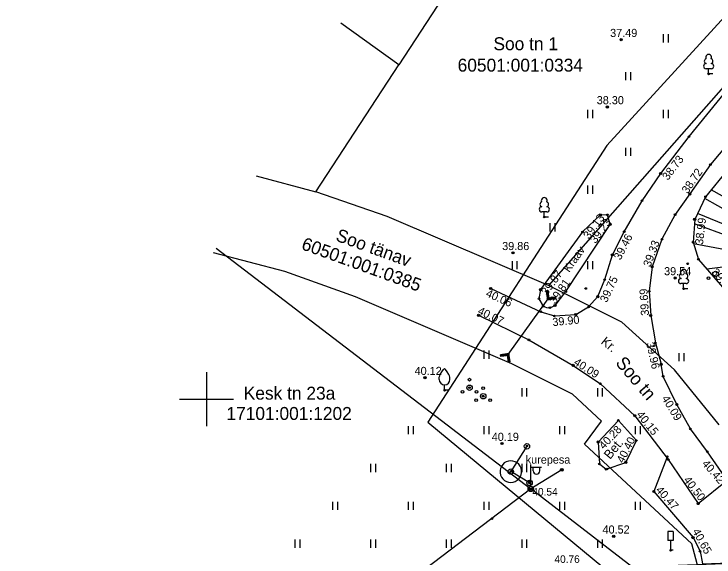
# Model space of a CAD drawing. Extents: x 641898 to 642452, y 6471715 to 6472255.
# Drawn here: x 641932.2 to 641997, y 6472085.4 to 6472135.7 of the extents above; entities that cross this region are included whole.
import ezdxf

# ---------------------------------------------------------------- set-up
doc = ezdxf.new("R2010")
doc.units = 0
for name, color, linetype in [('HALJASTUS', 7, 'Continuous'), ('KORGUS-EH2000', 7, 'Continuous'), ('LIIKLUS', 7, 'Continuous'), ('MOOTMPUNKT', 7, 'Continuous'), ('MOOTPIIR', 7, 'Continuous'), ('MPOHULIIN', 7, 'Continuous'), ('PIIR', 7, 'Continuous'), ('POST', 7, 'Continuous'), ('PUU', 7, 'Continuous'), ('RAJATIS', 7, 'Continuous'), ('RELJEEF', 7, 'Continuous'), ('TEE', 7, 'Continuous'), ('TRUUP', 7, 'Continuous'), ('VEEKOGU', 7, 'Continuous'), ('VORK', 7, 'Continuous')]:
    doc.layers.add(name, color=color, linetype=linetype)

msp = doc.modelspace()

# ---------------------------------------------------------------- linework, layer by layer
at = {"layer": 'HALJASTUS'}
for p, q in [((641992.275, 6472133.795), (641992.275, 6472133.034)), ((641992.73, 6472133.795), (641992.73, 6472133.034)), ((641988.775, 6472130.295), (641988.775, 6472129.534)), ((641989.23, 6472130.295), (641989.23, 6472129.534)), ((641985.275, 6472126.795), (641985.275, 6472126.034)), ((641985.73, 6472126.795), (641985.73, 6472126.034)), ((641992.275, 6472126.795), (641992.275, 6472126.034)), ((641992.73, 6472126.795), (641992.73, 6472126.034)), ((641988.775, 6472123.295), (641988.775, 6472122.534)), ((641989.23, 6472123.295), (641989.23, 6472122.534)), ((641985.275, 6472119.795), (641985.275, 6472119.034)), ((641985.73, 6472119.795), (641985.73, 6472119.034)), ((641981.775, 6472116.295), (641981.775, 6472115.534)), ((641982.23, 6472116.295), (641982.23, 6472115.534)), ((641978.275, 6472112.795), (641978.275, 6472112.034)), ((641978.73, 6472112.795), (641978.73, 6472112.034)), ((641985.275, 6472112.795), (641985.275, 6472112.034)), ((641985.73, 6472112.795), (641985.73, 6472112.034)), ((641975.672, 6472104.518), (641975.672, 6472103.757)), ((641976.127, 6472104.518), (641976.127, 6472103.757)), ((641993.725, 6472104.282), (641993.725, 6472103.521)), ((641994.18, 6472104.282), (641994.18, 6472103.521)), ((641979.172, 6472101.018), (641979.172, 6472100.257)), ((641979.627, 6472101.018), (641979.627, 6472100.257)), ((641986.172, 6472101.018), (641986.172, 6472100.257)), ((641986.627, 6472101.018), (641986.627, 6472100.257)), ((641968.672, 6472097.518), (641968.672, 6472096.757)), ((641969.127, 6472097.518), (641969.127, 6472096.757)), ((641975.672, 6472097.518), (641975.672, 6472096.757)), ((641976.127, 6472097.518), (641976.127, 6472096.757)), ((641982.672, 6472097.518), (641982.672, 6472096.757)), ((641983.127, 6472097.518), (641983.127, 6472096.757)), ((641989.672, 6472097.518), (641989.672, 6472096.757)), ((641990.127, 6472097.518), (641990.127, 6472096.757)), ((641965.172, 6472094.018), (641965.172, 6472093.257)), ((641965.627, 6472094.018), (641965.627, 6472093.257)), ((641972.172, 6472094.018), (641972.172, 6472093.257)), ((641972.627, 6472094.018), (641972.627, 6472093.257)), ((641979.172, 6472094.018), (641979.172, 6472093.257)), ((641979.627, 6472094.018), (641979.627, 6472093.257)), ((641961.672, 6472090.518), (641961.672, 6472089.757)), ((641962.127, 6472090.518), (641962.127, 6472089.757)), ((641968.672, 6472090.518), (641968.672, 6472089.757)), ((641969.127, 6472090.518), (641969.127, 6472089.757)), ((641975.672, 6472090.518), (641975.672, 6472089.757)), ((641976.127, 6472090.518), (641976.127, 6472089.757)), ((641982.672, 6472090.518), (641982.672, 6472089.757)), ((641983.127, 6472090.518), (641983.127, 6472089.757)), ((641989.672, 6472090.518), (641989.672, 6472089.757)), ((641990.127, 6472090.518), (641990.127, 6472089.757)), ((641958.172, 6472087.018), (641958.172, 6472086.257)), ((641958.627, 6472087.018), (641958.627, 6472086.257)), ((641965.172, 6472087.018), (641965.172, 6472086.257)), ((641965.627, 6472087.018), (641965.627, 6472086.257)), ((641972.172, 6472087.018), (641972.172, 6472086.257)), ((641972.627, 6472087.018), (641972.627, 6472086.257)), ((641979.172, 6472087.018), (641979.172, 6472086.257)), ((641979.627, 6472087.018), (641979.627, 6472086.257)), ((641986.172, 6472087.018), (641986.172, 6472086.257)), ((641986.627, 6472087.018), (641986.627, 6472086.257))]:
    msp.add_line(p, q, dxfattribs=at)
at = {"layer": 'KORGUS-EH2000'}
for centre, radius in [((641988.375, 6472133.297), 0.1), ((641987.099, 6472127.07), 0.1), ((641992.04, 6472120.908), 0.1), ((641994.733, 6472119.014), 0.1), ((641986.443, 6472117.057), 0.1), ((641995.182, 6472116.657), 0.1), ((641987.363, 6472116.197), 0.1), ((641978.365, 6472113.566), 0.1), ((641987.56, 6472113.374), 0.1), ((641991.25, 6472112.263), 0.1), ((641993.372, 6472111.236), 0.1), ((641976.302, 6472110.256), 0.1), ((641980.906, 6472110.153), 0.1), ((641986.222, 6472109.509), 0.1), ((641982.253, 6472108.683), 0.1), ((641975.171, 6472107.781), 0.1), ((641984.167, 6472107.856), 0.1), ((641991.111, 6472107.763), 0.1), ((641983.935, 6472103.138), 0.1), ((641992.086, 6472103.239), 0.1), ((641970.218, 6472102.005), 0.1), ((641993.534, 6472099.522), 0.1), ((641989.645, 6472098.476), 0.1), ((641977.341, 6472095.901), 0.1), ((641986.252, 6472096.039), 0.1), ((641988.81, 6472094.161), 0.1), ((641982.888, 6472093.473), 0.125), ((641979.933, 6472091.622), 0.125), ((641991.404, 6472091.461), 0.1), ((641995.507, 6472090.345), 0.1), ((641987.687, 6472087.319), 0.1), ((641995.031, 6472087.196), 0.1)]:
    msp.add_circle(centre, radius, dxfattribs=at)
at = {"layer": 'LIIKLUS'}
for p, q in [((641992.702, 6472087.767), (641992.702, 6472086.917)), ((641993.202, 6472087.767), (641992.702, 6472087.767)), ((641993.202, 6472087.767), (641993.202, 6472086.917)), ((641993.202, 6472086.917), (641992.702, 6472086.917)), ((641992.952, 6472086.917), (641992.952, 6472086.017)), ((641993.202, 6472086.017), (641992.952, 6472086.017))]:
    msp.add_line(p, q, dxfattribs=at)
at = {"layer": 'MOOTMPUNKT'}
for centre in [(641988.375, 6472133.297), (641996.474, 6472130.131), (641987.099, 6472127.07), (641994.664, 6472124.321), (641996.641, 6472121.738), (641992.04, 6472120.908), (641994.733, 6472119.014), (641996.189, 6472118.754), (641990.306, 6472118.382), (641981.261, 6472116.877), (641986.443, 6472117.057), (641987.119, 6472117.081), (641993.369, 6472117.104), (641995.182, 6472116.657), (641987.363, 6472116.197), (641984.799, 6472115.492), (641988.66, 6472115.515), (641992.15, 6472114.815), (641995.043, 6472114.545), (641978.365, 6472113.566), (641987.56, 6472113.374), (641995.53, 6472112.953), (641991.25, 6472112.263), (641994.539, 6472112.549), (641986.855, 6472111.08), (641993.372, 6472111.236), (641976.302, 6472110.256), (641980.906, 6472110.153), (641985.101, 6472110.259), (641990.982, 6472110.001), (641994.155, 6472110.234), (641983.251, 6472109.967), (641986.222, 6472109.509), (641980.765, 6472109.307), (641981.618, 6472109.3), (641980.938, 6472108.111), (641981.163, 6472108.618), (641981.776, 6472108.477), (641982.253, 6472108.683), (641985.364, 6472108.549), (641975.171, 6472107.781), (641982.193, 6472107.714), (641984.167, 6472107.856), (641991.111, 6472107.763), (641979.834, 6472105.5), (641991.416, 6472104.95), (641991.546, 6472105.216), (641977.918, 6472104.147), (641983.935, 6472103.138), (641992.086, 6472103.239), (641970.218, 6472102.005), (641992.261, 6472102.125), (641974.342, 6472101.069), (641986.452, 6472101.438), (641972.034, 6472100.842), (641975.609, 6472100.284), (641993.534, 6472099.522), (641989.645, 6472098.476), (641988.123, 6472098.047), (641994.781, 6472097.254), (641977.341, 6472095.901), (641986.252, 6472096.039), (641989.788, 6472096.186), (641979.656, 6472095.684), (641996.353, 6472095.149), (641992.658, 6472094.68), (641986.365, 6472094.017), (641988.81, 6472094.161), (641992.737, 6472094.423), (641978.198, 6472093.324), (641982.905, 6472093.473), (641986.991, 6472093.52), (641987.055, 6472093.54), (641979.899, 6472092.264), (641979.906, 6472092.419), (641979.989, 6472091.716), (641980.101, 6472091.695), (641991.404, 6472091.461), (641995.507, 6472090.345), (641976.421, 6472088.939), (641987.687, 6472087.319), (641995.031, 6472087.196), (641992.952, 6472086.017), (641995.679, 6472085.928)]:
    msp.add_circle(centre, 0.075, dxfattribs=at)
at = {"layer": 'MOOTPIIR'}
msp.add_lwpolyline([(642014.306, 6472085.384), (642027.67, 6472104.979), (642055.501, 6472084.843), (642081.563, 6472094.262), (642123.938, 6472142.273), (642065.721, 6472244.475), (642008.922, 6472196.948), (642003.347, 6472200.453), (641979.65, 6472162.756), (641979.65, 6472162.756), (641986.045, 6472158.736), (642004.269, 6472142.365), (641987.048, 6472123.488), (641970.482, 6472097.889), (641986.758, 6472084.396)], close=True, dxfattribs=at)
at = {"layer": 'MPOHULIIN'}
msp.add_line((641950.884, 6472113.984), (641980.015, 6472091.706), dxfattribs=at)
msp.add_lwpolyline([(642355.522, 6471813.313), (642331.534, 6471832.393), (642302.222, 6471855.921), (642271.629, 6471880.301), (642234.793, 6471909.555), (642198.436, 6471939.015), (642169.975, 6471961.956), (642133.076, 6471995.171), (642102.99, 6472021.089), (642074.552, 6472045.947), (642044.597, 6472041.824), (642019.939, 6472060.923), (641980.015, 6472091.706), (641945.513, 6472065.466), (641932.178, 6472056.628)], dxfattribs=at)
at = {"layer": 'PIIR'}
for p, q in [((642000.12, 6472180.55), (641967.79, 6472130.98)), ((642028, 6472163.22), (641981.64, 6472110.54)), ((641967.79, 6472130.98), (641962.432, 6472134.816)), ((641960.12, 6472119.21), (641967.79, 6472130.98)), ((641954.607, 6472120.7), (641960.12, 6472119.21)), ((641966.72, 6472116.93), (641960.12, 6472119.21)), ((641981.64, 6472110.54), (641966.72, 6472116.93)), ((641957.25, 6472111.83), (641950.653, 6472113.567)), ((641963.79, 6472109.48), (641957.25, 6472111.83)), ((641988.43, 6472107.13), (641981.64, 6472110.54)), ((641978.27, 6472103.28), (641963.79, 6472109.48)), ((641993.3, 6472102.74), (641988.43, 6472107.13)), ((641983.87, 6472100.47), (641978.27, 6472103.28)), ((641997.45, 6472097.63), (641993.3, 6472102.74)), ((641986.57, 6472097.97), (641983.87, 6472100.47)), ((641984.97, 6472095.85), (641986.57, 6472097.97)), ((641994.93, 6472086.61), (641984.97, 6472095.85)), ((641995.74, 6472083.5), (641994.93, 6472086.61))]:
    msp.add_line(p, q, dxfattribs=at)
at = {"layer": 'POST'}
for p, q in [((641979.658, 6472095.648), (641978.16, 6472093.303)), ((641980.015, 6472091.956), (641980.015, 6472093.956)), ((641979.899, 6472092.264), (641978.16, 6472093.303)), ((641980.015, 6472093.706), (641981.015, 6472093.706)), ((641982.888, 6472093.473), (641980.015, 6472091.706)), ((641980.242, 6472093.385), (641980.242, 6472093.706)), ((641980.854, 6472093.385), (641980.854, 6472093.706)), ((641980.015, 6472091.706), (641980.015, 6472091.706))]:
    msp.add_line(p, q, dxfattribs=at)
for centre, radius in [((641979.658, 6472095.648), 0.25), ((641978.16, 6472093.303), 0.25), ((641982.888, 6472093.473), 0.125), ((641982.888, 6472093.473), 0.117), ((641982.888, 6472093.473), 0.109), ((641982.888, 6472093.473), 0.102), ((641982.888, 6472093.473), 0.0938), ((641982.888, 6472093.473), 0.086), ((641982.888, 6472093.473), 0.0782), ((641982.888, 6472093.473), 0.0704), ((641982.888, 6472093.473), 0.0626), ((641982.888, 6472093.473), 0.0548), ((641982.888, 6472093.473), 0.047), ((641982.888, 6472093.473), 0.0392), ((641982.888, 6472093.473), 0.0314), ((641982.888, 6472093.473), 0.0236), ((641982.888, 6472093.473), 0.0158), ((641982.888, 6472093.473), 0.00798), ((641982.888, 6472093.473), 0.000186), ((641979.899, 6472092.264), 0.25), ((641980.015, 6472091.706), 0.25)]:
    msp.add_circle(centre, radius, dxfattribs=at)
msp.add_arc((641980.548, 6472093.385), 0.306, 180, 0, dxfattribs=at)
at = {"layer": 'PUU'}
for p, q in [((641996.714, 6472130.606), (641996.234, 6472130.606)), ((641996.474, 6472130.131), (641996.474, 6472130.606)), ((641996.854, 6472130.131), (641996.474, 6472130.131)), ((641981.501, 6472117.352), (641981.021, 6472117.352)), ((641981.261, 6472116.877), (641981.261, 6472117.352)), ((641981.641, 6472116.877), (641981.261, 6472116.877)), ((641994.395, 6472110.709), (641993.915, 6472110.709)), ((641994.155, 6472110.234), (641994.155, 6472110.709)), ((641994.535, 6472110.234), (641994.155, 6472110.234)), ((641972.034, 6472100.842), (641972.034, 6472101.342)), ((641972.434, 6472100.842), (641972.034, 6472100.842))]:
    msp.add_line(p, q, dxfattribs=at)
for points in [[(641971.534, 6472101.842), (641971.534, 6472101.992), (641971.544, 6472102.057), (641971.579, 6472102.187), (641971.639, 6472102.307), (641971.784, 6472102.542), (641971.944, 6472102.747), (641972.034, 6472102.842)], [(641972.534, 6472101.842), (641972.534, 6472101.992), (641972.524, 6472102.057), (641972.489, 6472102.187), (641972.429, 6472102.307), (641972.284, 6472102.542), (641972.124, 6472102.747), (641972.034, 6472102.842)]]:
    msp.add_lwpolyline(points, dxfattribs=at)
for centre, radius in [((641997.116, 6472111.599), 0.25), ((641996.466, 6472111.224), 0.125), ((641974.342, 6472101.819), 0.125), ((641974.342, 6472101.069), 0.25), ((641975.609, 6472101.034), 0.125), ((641973.692, 6472100.694), 0.125), ((641974.992, 6472100.694), 0.125), ((641975.609, 6472100.284), 0.25), ((641974.959, 6472099.909), 0.125), ((641976.259, 6472099.909), 0.125)]:
    msp.add_circle(centre, radius, dxfattribs=at)
for centre, radius, start, end in [((641996.304, 6472131.304), 0.233, 109.02174, 253.14154), ((641996.474, 6472131.651), 0.277, 332.5799, 207.4201), ((641996.644, 6472131.304), 0.233, 286.85082, 70.98591), ((641996.237, 6472130.843), 0.238, 90.0016, 269.3953), ((641996.711, 6472130.843), 0.238, 270.6047, 89.9984), ((641981.261, 6472118.397), 0.277, 332.5799, 207.4201), ((641981.091, 6472118.05), 0.233, 109.02174, 253.14154), ((641981.431, 6472118.05), 0.233, 286.85082, 70.98591), ((641981.024, 6472117.589), 0.238, 90.0016, 269.3953), ((641981.498, 6472117.589), 0.238, 270.6047, 89.9984), ((641994.155, 6472111.754), 0.277, 332.5799, 207.4201), ((641993.985, 6472111.407), 0.233, 109.02174, 253.14154), ((641994.325, 6472111.407), 0.233, 286.85082, 70.98591), ((641993.918, 6472110.946), 0.238, 90.0016, 269.3953), ((641994.392, 6472110.946), 0.238, 270.6047, 89.9984), ((641972.034, 6472101.842), 0.5, 180, 0)]:
    msp.add_arc(centre, radius, start, end, dxfattribs=at)
at = {"layer": 'RAJATIS'}
msp.add_lwpolyline([(641978.578, 6472092.394), (641978.758, 6472092.501), (641978.911, 6472092.643), (641979.032, 6472092.814), (641979.115, 6472093.006), (641979.156, 6472093.211), (641979.153, 6472093.42), (641979.107, 6472093.624), (641979.02, 6472093.813), (641978.895, 6472093.981), (641978.738, 6472094.119), (641978.556, 6472094.221), (641978.356, 6472094.284), (641978.148, 6472094.303), (641977.94, 6472094.279), (641977.742, 6472094.212), (641977.562, 6472094.105), (641977.409, 6472093.963), (641977.288, 6472093.792), (641977.205, 6472093.6), (641977.164, 6472093.395), (641977.167, 6472093.186), (641977.213, 6472092.982), (641977.3, 6472092.793), (641977.425, 6472092.625), (641977.582, 6472092.487), (641977.764, 6472092.385), (641977.964, 6472092.322), (641978.172, 6472092.303), (641978.38, 6472092.327)], close=True, dxfattribs=at)
at = {"layer": 'RELJEEF'}
for p, q in [((642004.576, 6472114.968), (641996.718, 6472119.397)), ((642003.919, 6472114.19), (641996.111, 6472118.591)), ((642003.656, 6472113.811), (641995.446, 6472117.206)), ((642003.259, 6472113.239), (641995.155, 6472116.244)), ((642003.015, 6472112.887), (641995.086, 6472114.406)), ((642003.015, 6472112.887), (641996.316, 6472112.052))]:
    msp.add_line(p, q, dxfattribs=at)
msp.add_lwpolyline([(641998.265, 6472121.279), (641996.189, 6472118.754), (641995.182, 6472116.657), (641995.043, 6472114.545), (641995.53, 6472112.953), (641997.98, 6472110.147)], dxfattribs=at)
at = {"layer": 'TEE'}
for points in [[(641976.302, 6472110.256), (641980.938, 6472108.111), (641982.193, 6472107.714), (641984.167, 6472107.856), (641985.364, 6472108.549), (641986.222, 6472109.509), (641986.855, 6472111.08), (641987.56, 6472113.374), (641988.66, 6472115.515), (641990.306, 6472118.382), (641992.04, 6472120.908), (641994.664, 6472124.321), (641998.234, 6472128.673)], [(642000.657, 6472126.535), (641996.641, 6472121.738), (641994.733, 6472119.014), (641993.369, 6472117.104), (641992.15, 6472114.815), (641991.25, 6472112.263), (641990.982, 6472110.001), (641991.111, 6472107.763), (641991.546, 6472105.216), (641992.086, 6472103.239)], [(641975.171, 6472107.781), (641979.834, 6472105.5), (641983.935, 6472103.138), (641986.452, 6472101.438), (641989.645, 6472098.476), (641992.737, 6472094.423), (641995.507, 6472090.345), (641998.193, 6472092.499), (641996.353, 6472095.149), (641994.781, 6472097.254), (641993.534, 6472099.522), (641992.261, 6472102.125), (641992.086, 6472103.239)], [(641986.991, 6472093.52), (641988.81, 6472094.161), (641989.788, 6472096.186), (641988.123, 6472098.047), (641986.252, 6472096.039), (641986.365, 6472094.017), (641986.991, 6472093.52)], [(641992.618, 6472094.578), (641991.404, 6472091.461), (641995.031, 6472087.196), (641995.679, 6472085.928), (641995.92, 6472084.762), (642004.997, 6472085.116), (642001.868, 6472088.221), (641999.18, 6472091.513), (641998.193, 6472092.499)]]:
    msp.add_lwpolyline(points, dxfattribs=at)
at = {"layer": 'TRUUP'}
for p, q in [((641981.574, 6472110.009), (641981.433, 6472109.986)), ((641981.433, 6472109.986), (641981.559, 6472109.218)), ((641981.462, 6472109.991), (641981.443, 6472109.929)), ((641981.49, 6472109.996), (641981.452, 6472109.874)), ((641981.517, 6472110), (641981.461, 6472109.819)), ((641981.545, 6472110.005), (641981.47, 6472109.764)), ((641981.573, 6472110.009), (641981.479, 6472109.709)), ((641981.582, 6472109.956), (641981.488, 6472109.655)), ((641981.591, 6472109.902), (641981.497, 6472109.6)), ((641981.503, 6472109.998), (641981.618, 6472109.3)), ((641981.6, 6472109.847), (641981.506, 6472109.545)), ((641981.609, 6472109.792), (641981.515, 6472109.49)), ((641981.618, 6472109.737), (641981.524, 6472109.435)), ((641981.627, 6472109.682), (641981.533, 6472109.38)), ((641981.636, 6472109.628), (641981.542, 6472109.326)), ((641981.645, 6472109.573), (641981.551, 6472109.271)), ((641981.654, 6472109.518), (641981.56, 6472109.218)), ((641981.574, 6472110.009), (641981.677, 6472109.382)), ((641981.663, 6472109.463), (641981.588, 6472109.223)), ((641981.677, 6472109.382), (641982.304, 6472109.485)), ((641981.94, 6472109.425), (641981.892, 6472109.273)), ((641981.967, 6472109.429), (641981.92, 6472109.277)), ((641981.995, 6472109.434), (641981.947, 6472109.282)), ((641982.023, 6472109.439), (641981.975, 6472109.286)), ((641982.05, 6472109.443), (641982.002, 6472109.291)), ((641982.078, 6472109.448), (641982.03, 6472109.295)), ((641982.105, 6472109.452), (641982.058, 6472109.3)), ((641982.133, 6472109.457), (641982.085, 6472109.305)), ((641982.161, 6472109.461), (641982.113, 6472109.309)), ((641982.188, 6472109.466), (641982.141, 6472109.314)), ((641982.216, 6472109.47), (641982.168, 6472109.318)), ((641982.244, 6472109.475), (641982.196, 6472109.323)), ((641982.271, 6472109.479), (641982.223, 6472109.327)), ((641982.299, 6472109.484), (641982.251, 6472109.332)), ((641982.311, 6472109.441), (641982.279, 6472109.336)), ((641982.304, 6472109.485), (641982.327, 6472109.344)), ((641981.559, 6472109.218), (641982.327, 6472109.344)), ((641981.672, 6472109.408), (641981.616, 6472109.227)), ((641981.618, 6472109.3), (641982.316, 6472109.415)), ((641981.691, 6472109.384), (641981.643, 6472109.232)), ((641981.719, 6472109.389), (641981.671, 6472109.237)), ((641981.746, 6472109.393), (641981.699, 6472109.241)), ((641981.774, 6472109.398), (641981.726, 6472109.246)), ((641981.802, 6472109.402), (641981.754, 6472109.25)), ((641981.829, 6472109.407), (641981.781, 6472109.255)), ((641981.857, 6472109.411), (641981.809, 6472109.259)), ((641981.884, 6472109.416), (641981.837, 6472109.264)), ((641981.912, 6472109.42), (641981.864, 6472109.268)), ((641982.32, 6472109.386), (641982.306, 6472109.341)), ((641977.977, 6472104.229), (641977.209, 6472104.103)), ((641977.232, 6472103.962), (641977.209, 6472104.103)), ((641977.216, 6472104.061), (641977.23, 6472104.106)), ((641977.918, 6472104.147), (641977.22, 6472104.032)), ((641977.225, 6472104.006), (641977.257, 6472104.111)), ((641977.859, 6472104.065), (641977.232, 6472103.962)), ((641977.237, 6472103.963), (641977.285, 6472104.115)), ((641977.265, 6472103.968), (641977.313, 6472104.12)), ((641977.292, 6472103.972), (641977.34, 6472104.124)), ((641977.32, 6472103.977), (641977.368, 6472104.129)), ((641977.348, 6472103.981), (641977.395, 6472104.133)), ((641977.375, 6472103.986), (641977.423, 6472104.138)), ((641977.403, 6472103.99), (641977.451, 6472104.142)), ((641977.431, 6472103.995), (641977.478, 6472104.147)), ((641977.458, 6472103.999), (641977.506, 6472104.152)), ((641977.486, 6472104.004), (641977.534, 6472104.156)), ((641977.513, 6472104.008), (641977.561, 6472104.161)), ((641977.541, 6472104.013), (641977.589, 6472104.165)), ((641977.569, 6472104.018), (641977.616, 6472104.17)), ((641977.596, 6472104.022), (641977.644, 6472104.174)), ((641977.624, 6472104.027), (641977.672, 6472104.179)), ((641977.652, 6472104.031), (641977.699, 6472104.183)), ((641977.679, 6472104.036), (641977.727, 6472104.188)), ((641977.707, 6472104.04), (641977.755, 6472104.192)), ((641977.734, 6472104.045), (641977.782, 6472104.197)), ((641977.762, 6472104.049), (641977.81, 6472104.201)), ((641977.79, 6472104.054), (641977.837, 6472104.206)), ((641977.817, 6472104.058), (641977.865, 6472104.21)), ((641977.845, 6472104.063), (641977.893, 6472104.215)), ((641977.962, 6472103.438), (641977.859, 6472104.065)), ((641977.864, 6472104.039), (641977.92, 6472104.22)), ((641977.873, 6472103.984), (641977.948, 6472104.224)), ((641977.882, 6472103.929), (641977.976, 6472104.229)), ((641977.891, 6472103.874), (641977.985, 6472104.176)), ((641977.9, 6472103.819), (641977.994, 6472104.121)), ((641977.909, 6472103.765), (641978.003, 6472104.067)), ((641978.033, 6472103.449), (641977.918, 6472104.147)), ((641977.918, 6472103.71), (641978.012, 6472104.012)), ((641977.927, 6472103.655), (641978.021, 6472103.957)), ((641977.936, 6472103.6), (641978.03, 6472103.902)), ((641977.945, 6472103.545), (641978.039, 6472103.847)), ((641977.954, 6472103.491), (641978.048, 6472103.792)), ((641977.963, 6472103.438), (641978.057, 6472103.738)), ((641978.103, 6472103.461), (641977.977, 6472104.229)), ((641977.991, 6472103.442), (641978.066, 6472103.683)), ((641978.019, 6472103.447), (641978.075, 6472103.628)), ((641977.962, 6472103.438), (641978.103, 6472103.461)), ((641978.046, 6472103.451), (641978.084, 6472103.573)), ((641978.074, 6472103.456), (641978.093, 6472103.518))]:
    msp.add_line(p, q, dxfattribs=at)
msp.add_lwpolyline([(641977.918, 6472104.147), (641981.618, 6472109.3)], dxfattribs=at)
at = {"layer": 'VEEKOGU'}
msp.add_lwpolyline([(641981.776, 6472108.477), (641982.253, 6472108.683), (641983.251, 6472109.967), (641987.363, 6472116.197), (641987.119, 6472117.081), (641986.443, 6472117.057), (641984.799, 6472115.492), (641980.906, 6472110.153), (641980.765, 6472109.307), (641981.163, 6472108.618), (641981.457, 6472108.488), (641981.776, 6472108.477)], dxfattribs=at)
at = {"layer": 'VORK'}
for p, q in [((641950, 6472102.5), (641950, 6472097.5)), ((641947.5, 6472100), (641952.5, 6472100))]:
    msp.add_line(p, q, dxfattribs=at)

# ---------------------------------------------------------------- texts
at = {"layer": 'KORGUS-EH2000'}
for s, height, p in [('37.49', 0.75, (641987.357, 6472133.547)), ('38.30', 0.75, (641986.117, 6472127.32)), ('39.86', 0.75, (641977.363, 6472113.816)), ('39.54', 0.75, (641992.351, 6472111.486)), ('40.12', 0.75, (641969.258, 6472102.255)), ('40.19', 0.75, (641976.398, 6472096.151)), ('40.54', 0.7, (641980.156, 6472091.086)), ('40.52', 0.75, (641986.652, 6472087.569)), ('40.76', 0.7, (641982.201, 6472084.85))]:
    msp.add_text(s, height=height, dxfattribs=at).set_placement(p)
for s, rotation, p in [('38.73', 52.78145, (641992.701, 6472120.22)), ('38.72', 55.64494, (641994.536, 6472118.974)), ('39.13', 53.71, (641985.404, 6472114.772)), ('39.23', 52.77548, (641986.005, 6472114.37)), ('38.99', 83.09607, (641995.943, 6472114.271)), ('39.46', 62.61134, (641988.31, 6472112.832)), ('39.33', 69.52838, (641991.082, 6472112.194)), ('39.55', 312.02772, (641996.679, 6472111.724)), ('39.87', 53.85025, (641981.51, 6472109.57)), ('39.75', 64.98958, (641987.046, 6472108.902)), ('39.81', 54.93007, (641982.263, 6472108.754)), ('40.06', 335.88309, (641975.786, 6472109.551)), ('39.69', 93.40812, (641990.959, 6472107.76)), ('40.07', 334.28779, (641975.027, 6472107.937)), ('39.90', 5.78149, (641982.051, 6472106.767)), ('39.96', 282.83097, (641990.681, 6472105.189)), ('40.09', 327.45494, (641983.918, 6472103.254)), ('40.09', 301.55409, (641992.102, 6472100.07)), ('40.15', 308.6158, (641989.751, 6472098.549)), ('40.28', 46.88545, (641986.772, 6472095.31)), ('40.40', 63.07285, (641988.578, 6472094.027)), ('40.42', 311.05756, (641995.807, 6472094.001)), ('40.50', 307.52645, (641994.113, 6472092.515)), ('40.47', 311.68524, (641991.531, 6472091.555)), ('40.65', 298.74924, (641994.946, 6472087.778))]:
    msp.add_text(s, height=0.75, rotation=rotation, dxfattribs=at).set_placement(p)
at = {"layer": 'PIIR'}
for s, p in [('Soo tn 1', (641976.555, 6472132.321)), ('60501:001:0334', (641973.241, 6472130.337)), ('Kesk tn 23a', (641953.443, 6472099.968)), ('17101:001:1202', (641951.843, 6472098.088))]:
    msp.add_text(s, height=1.2, dxfattribs=at).set_placement(p)
for s, p in [('Soo tänav', (641961.874, 6472114.711)), ('60501:001:0385', (641958.697, 6472113.916))]:
    msp.add_text(s, height=1.2, rotation=340.03255, dxfattribs=at).set_placement(p)
at = {"layer": 'RAJATIS'}
msp.add_text('kurepesa', height=0.75, dxfattribs=at).set_placement((641979.545, 6472094.042))
at = {"layer": 'TEE'}
for s, height, rotation, p in [('Kr.', 0.85, 320.75422, (641986.433, 6472105.213)), ('Soo tn', 1.2, 310.42375, (641987.791, 6472103.332)), ('Bet.', 0.85, 50.54375, (641987.351, 6472094.384))]:
    msp.add_text(s, height=height, rotation=rotation, dxfattribs=at).set_placement(p)
at = {"layer": 'VEEKOGU'}
msp.add_text('Kraav', height=0.75, rotation=54.82165, dxfattribs=at).set_placement((641983.565, 6472111.694))

doc.saveas('drawing.dxf')
